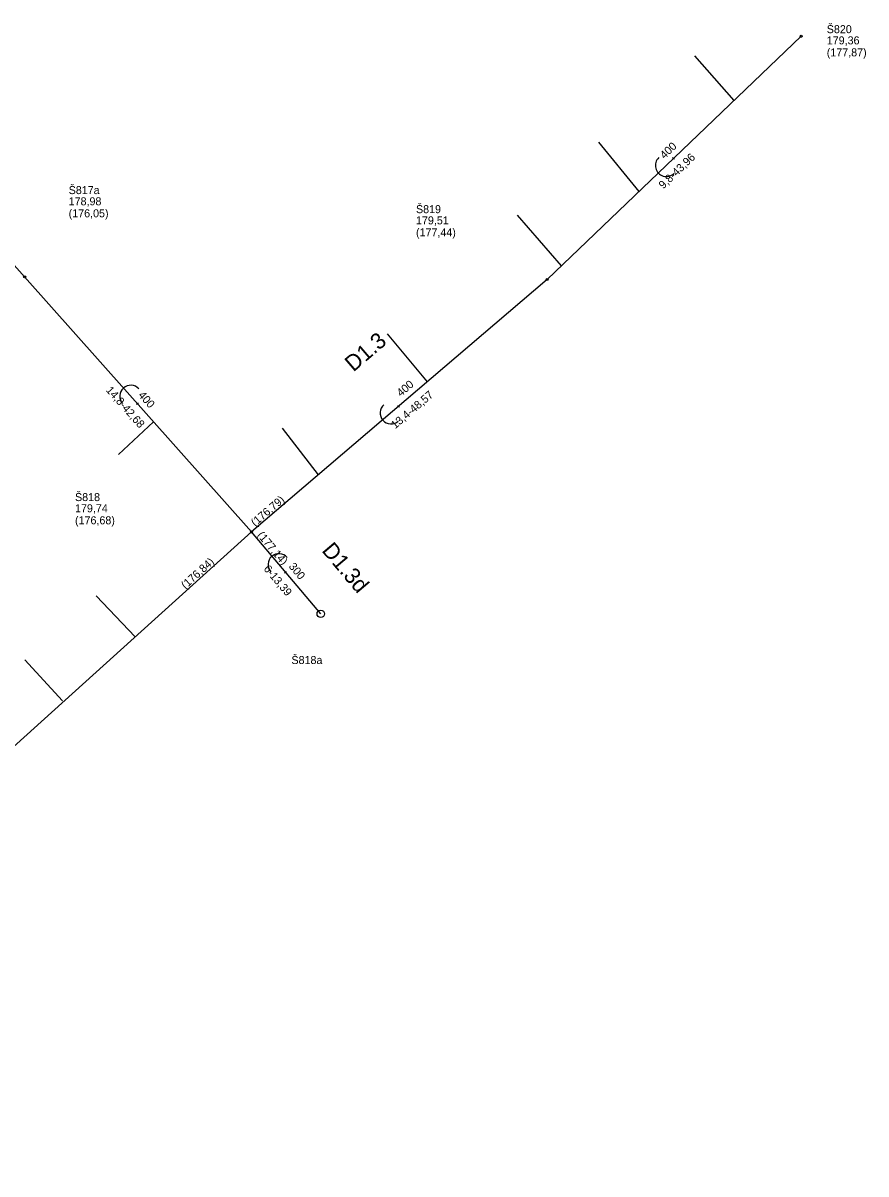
# Model space of a CAD drawing. Extents: x -548529 to -543591, y -1201432 to -1192608.
# Drawn here: x -544931.3 to -544826, y -1193960 to -1193816.1 of the extents above; entities that cross this region are included whole.
import ezdxf

# ---------------------------------------------------------------- set-up
doc = ezdxf.new("R2010")
doc.units = 0
for name, color, linetype in [('C3D_Bod-Značky', 7, 'Continuous'), ('C3D_Koridor', 7, 'Continuous'), ('C3D_Křižovatka', 7, 'Continuous'), ('C3D_Netisknutelná', 7, 'Continuous'), ('C3D_PP-zobrazeni v PR', 7, 'Continuous'), ('C3D_PR-Popisek', 7, 'Continuous'), ('C3D_SPR-Popisek', 7, 'Continuous'), ('C3D_Tlakove_potrubi_Popis', 7, 'Continuous'), ('C3D_ZPR-Formaty', 7, 'Continuous')]:
    doc.layers.add(name, color=color, linetype=linetype)

# ---------------------------------------------------------------- blocks, each defined once
blk = doc.blocks.new('100')
at = {"layer": 'Defpoints'}
blk.add_circle((0, 0), 0.127, dxfattribs=at)
blk = doc.blocks.new('101')
at = {"layer": 'Defpoints'}
blk.add_circle((0, 0), 0.463, dxfattribs=at)
blk = doc.blocks.new('91')
at = {"layer": 'Defpoints'}
blk.add_lwpolyline([(0.08, 0.14), (0.19, 0), (0.08, -0.14)], dxfattribs=at)
blk.add_arc((1.37, 0), 1.37, 270, 90, dxfattribs=at)

msp = doc.modelspace()

# ---------------------------------------------------------------- linework, layer by layer
at = {"layer": 'C3D_Bod-Značky'}
for points in [[(-544931.08, -1193847.85), (-544958.02, -1193817.44)], [(-544834.048, -1193817.799), (-544865.794, -1193848.202)], [(-544902.727, -1193879.747), (-544931.08, -1193847.85)], [(-544865.794, -1193848.202), (-544902.727, -1193879.747)], [(-544991.583, -1193959.982), (-544902.727, -1193879.747)], [(-544894.086, -1193889.972), (-544902.727, -1193879.747)]]:
    msp.add_lwpolyline(points, dxfattribs=at)
at = {"layer": 'C3D_Koridor'}
for points in [[(-544842.442, -1193825.838), (-544847.348, -1193820.246)], [(-544854.297, -1193837.192), (-544859.351, -1193831.027)], [(-544863.993, -1193846.477), (-544869.508, -1193840.153)], [(-544880.754, -1193860.98), (-544885.756, -1193854.994)], [(-544914.978, -1193865.965), (-544919.362, -1193870.064)], [(-544894.382, -1193872.62), (-544898.847, -1193866.782)], [(-544917.26, -1193892.87), (-544922.154, -1193887.729)], [(-544926.37, -1193900.845), (-544931.076, -1193895.745)]]:
    msp.add_lwpolyline(points, dxfattribs=at)

# ---------------------------------------------------------------- block references
at = {"layer": 'C3D_PP-zobrazeni v PR'}
for name, p, xscale, yscale, rotation in [('100', (-544834.048, -1193817.799), 1.0000000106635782, 1.0000000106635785, 44.00000165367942), ('100', (-544931.08, -1193847.85), 1.0000000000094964, 1.0000000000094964, 132.0000013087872), ('100', (-544865.794, -1193848.202), 1.00000000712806, 1.00000000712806, -136.99999943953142), ('100', (-544902.727, -1193879.747), 0.9999999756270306, 0.9999999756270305, -93.00000001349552), ('101', (-544894.086, -1193889.972), 1.0000000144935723, 1.0000000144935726, -49.00000089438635)]:
    msp.add_blockref(name, p, dxfattribs=dict(at, xscale=xscale, yscale=yscale, rotation=rotation))
at = {"layer": 'C3D_SPR-Popisek'}
for p, xscale, yscale, rotation in [((-544849.921, -1193833), 1.0000000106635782, 1.0000000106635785, -135.99999834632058), ((-544916.904, -1193863.798), 1.0000000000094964, 1.0000000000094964, 132.0000013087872), ((-544884.26, -1193863.974), 1.0000000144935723, 1.0000000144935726, -139.00000089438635), ((-544898.406, -1193884.86), 1.0000000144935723, 1.0000000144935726, 130.99999910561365)]:
    msp.add_blockref('91', p, dxfattribs=dict(at, xscale=xscale, yscale=yscale, rotation=rotation))

# ---------------------------------------------------------------- texts
at = {"layer": 'C3D_Křižovatka'}
for s, p in [('Š820', (-544830.858, -1193817.409)), ('Š817a', (-544925.58, -1193837.52)), ('Š819', (-544882.184, -1193839.902)), ('Š818', (-544924.787, -1193875.887)), ('Š818a', (-544897.746, -1193896.252))]:
    msp.add_text(s, height=1, dxfattribs=at).set_placement(p)
at = {"layer": 'C3D_Netisknutelná'}
for s, rotation, p in [('D1.3', 40.5, (-544890.005, -1193859.811)), ('D1.3d', 310.2, (-544894.04, -1193882.108))]:
    msp.add_text(s, height=2, rotation=rotation, dxfattribs=at).set_placement(p)
at = {"layer": 'C3D_PR-Popisek'}
for s, rotation, p in [('400', 43.76, (-544851.133, -1193833.189)), ('400', 40.5, (-544884.072, -1193862.898)), ('400', 311.63, (-544916.954, -1193862.694)), ('300', 310.2, (-544898.144, -1193884.091))]:
    msp.add_text(s, height=1, rotation=rotation, dxfattribs=at).set_placement(p)
at = {"layer": 'C3D_Tlakove_potrubi_Popis'}
for s, p in [('179,36 ', (-544830.858, -1193818.809)), ('(177,87)', (-544830.858, -1193820.309)), ('178,98 ', (-544925.58, -1193838.92)), ('(176,05)', (-544925.58, -1193840.42)), ('179,51 ', (-544882.184, -1193841.302)), ('(177,44)', (-544882.184, -1193842.802)), ('179,74 ', (-544924.787, -1193877.287)), ('(176,68)', (-544924.787, -1193878.787))]:
    msp.add_text(s, height=1, dxfattribs=at).set_placement(p)
at = {"layer": 'C3D_ZPR-Formaty'}
for s, rotation, p in [('9,8-43,96', 43.76, (-544851.285, -1193836.938)), ('14,8-42,68', 311.63, (-544920.983, -1193862.07)), ('13,4-48,57', 40.5, (-544884.788, -1193866.918)), ('  (176,79)   ', 40.5, (-544902.857, -1193879.595)), ('  (177,14)   ', 310.2, (-544902.574, -1193879.618)), ('  (176,84)   ', 42.08, (-544911.545, -1193887.44)), ('6-13,39', 310.2, (-544901.285, -1193884.39))]:
    msp.add_text(s, height=1, rotation=rotation, dxfattribs=at).set_placement(p)

doc.saveas('drawing.dxf')
